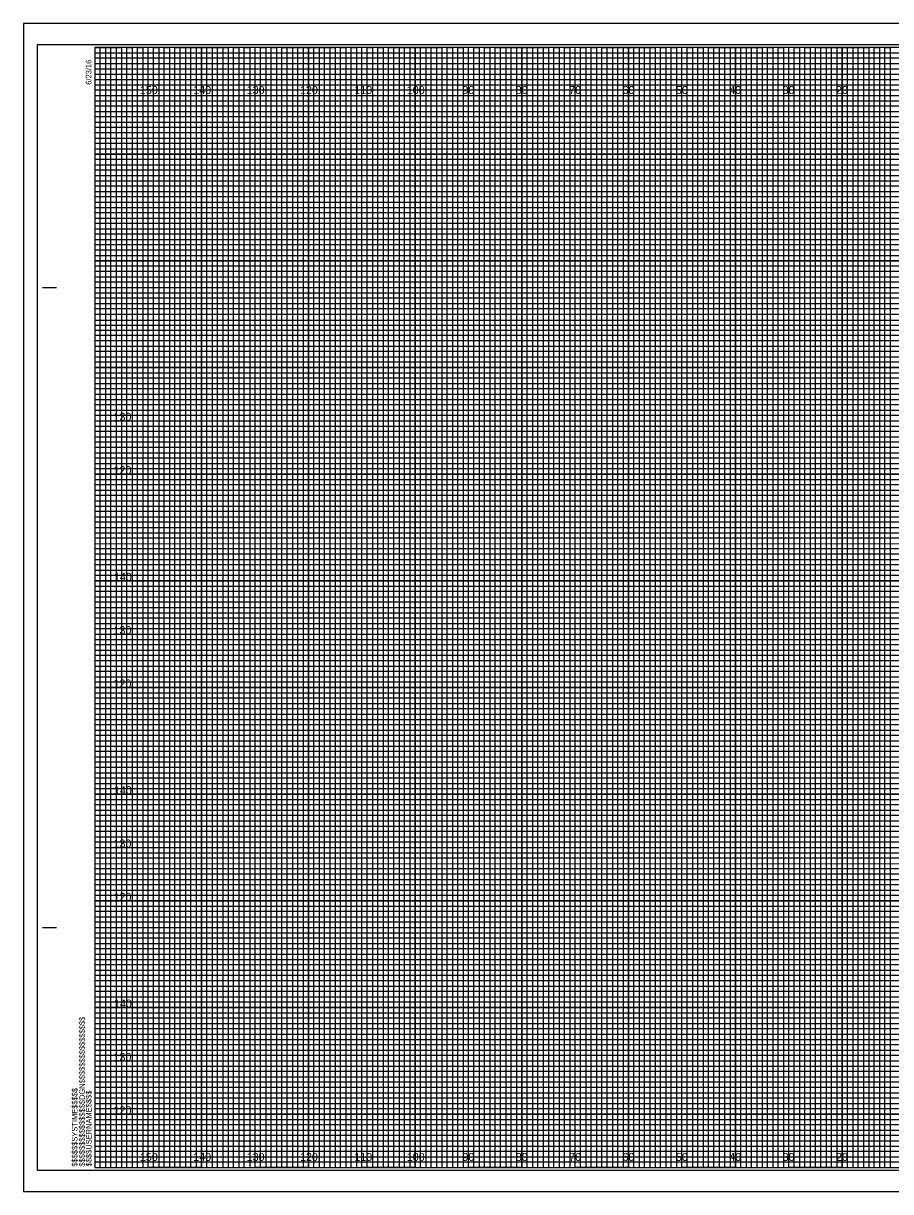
# Model space of a CAD drawing. Extents: x -13 to 323, y -5 to 215.
# Drawn here: x -13.4 to 149.1, y -4.5 to 214.5 of the extents above; entities that cross this region are included whole.
import ezdxf

# ---------------------------------------------------------------- set-up
doc = ezdxf.new("R2010")
doc.units = 0
for name, color, linetype in [('Exist CMT Pavement', 7, 'Continuous'), ('Exist Cross Section Cell', 7, 'Continuous'), ('Exist XS Center Line Elevation Label', 7, 'Continuous'), ('Exist XS Ground Line', 7, 'Continuous'), ('Prop CMT Concrete Structures', 7, 'Continuous'), ('Prop CMT Pvmt Course 1 Wedge', 7, 'Continuous'), ('Prop CMT Pvmt Course 2', 7, 'Continuous'), ('Prop CMT Pvmt Course 2 Wedge', 7, 'Continuous'), ('Prop CMT Pvmt Course 3', 7, 'Continuous'), ('Prop CMT Pvmt Course 3 Wedge', 7, 'Continuous'), ('Scratch_Level_0', 7, 'Continuous')]:
    doc.layers.add(name, color=color, linetype=linetype)

msp = doc.modelspace()

# ---------------------------------------------------------------- linework, layer by layer
at = {"layer": 'Exist XS Center Line Elevation Label'}
for points in [[(0, 210), (5, 210), (5, 0), (15, 0), (15, 210), (25, 210), (25, 0), (35, 0), (35, 210), (45, 210), (45, 0), (55, 0), (55, 210), (65, 210), (65, 0), (75, 0), (75, 210), (85, 210), (85, 0), (95, 0), (95, 210), (105, 210), (105, 0), (115, 0), (115, 210), (125, 210), (125, 0), (135, 0), (135, 210), (145, 210), (145, 0), (155, 0)], [(0, 205), (275, 205)], [(0, 185), (320, 185), (320, 195), (0, 195)], [(0, 165), (320, 165), (320, 175), (0, 175)], [(0, 145), (320, 145), (320, 155), (0, 155)], [(0, 125), (320, 125), (320, 135), (0, 135)], [(0, 105), (320, 105), (320, 115), (0, 115)], [(0, 85), (320, 85), (320, 95), (0, 95)], [(0, 65), (320, 65), (320, 75), (0, 75)], [(0, 45), (320, 45), (320, 55), (0, 55)], [(0, 25), (320, 25), (320, 35), (0, 35)], [(0, 5), (320, 5), (320, 15), (0, 15)]]:
    msp.add_lwpolyline(points, dxfattribs=at)
at = {"layer": 'Exist XS Ground Line'}
for p, q in [((10, 210), (0, 210)), ((10, 0), (10, 210)), ((30, 210), (20, 210)), ((20, 210), (20, 0)), ((30, 0), (30, 210)), ((50, 210), (40, 210)), ((40, 210), (40, 0)), ((50, 0), (50, 210)), ((70, 210), (60, 210)), ((60, 210), (60, 0)), ((70, 0), (70, 210)), ((90, 210), (80, 210)), ((80, 210), (80, 0)), ((90, 0), (90, 210)), ((110, 210), (100, 210)), ((100, 210), (100, 0)), ((110, 0), (110, 210)), ((130, 210), (120, 210)), ((120, 210), (120, 0)), ((130, 0), (130, 210)), ((150, 210), (140, 210)), ((140, 210), (140, 0)), ((20, 0), (10, 0)), ((40, 0), (30, 0)), ((60, 0), (50, 0)), ((80, 0), (70, 0)), ((100, 0), (90, 0)), ((120, 0), (110, 0)), ((140, 0), (130, 0))]:
    msp.add_line(p, q, dxfattribs=at)
for points in [[(0, 200), (320, 200), (320, 190), (0, 190)], [(0, 180), (320, 180), (320, 170), (0, 170)], [(0, 160), (320, 160), (320, 150), (0, 150)], [(0, 140), (320, 140), (320, 130), (0, 130)], [(0, 120), (320, 120), (320, 110), (0, 110)], [(0, 100), (320, 100), (320, 90), (0, 90)], [(0, 80), (320, 80), (320, 70), (0, 70)], [(0, 60), (320, 60), (320, 50), (0, 50)], [(0, 40), (320, 40), (320, 30), (0, 30)], [(0, 20), (320, 20), (320, 10), (0, 10)]]:
    msp.add_lwpolyline(points, dxfattribs=at)
at = {"layer": 'Prop CMT Concrete Structures'}
for p, q in [((323.3, 214.5), (-13.4, 214.5)), ((-13.4, 214.5), (-13.4, -4.5)), ((-13.4, -4.5), (323.3, -4.5))]:
    msp.add_line(p, q, dxfattribs=at)
at = {"layer": 'Prop CMT Pvmt Course 1 Wedge'}
msp.add_lwpolyline([(-13.4, -4.5), (323.3, -4.5), (323.3, 214.5), (-13.4, 214.5)], close=True, dxfattribs=at)
at = {"layer": 'Prop CMT Pvmt Course 2'}
for p, q in [((-9.8, 165), (-7.3, 165)), ((-9.7, 165), (-7.2, 165)), ((-9.8, 45), (-7.3, 45)), ((-9.7, 45), (-7.2, 45)), ((0, 0), (0, 0)), ((0, 0), (0, 0)), ((0, 0), (0, 0)), ((0, 0), (0, 0)), ((0, 0), (0, 0)), ((0, 0), (0, 0)), ((0, 0), (0, 0))]:
    msp.add_line(p, q, dxfattribs=at)
msp.add_lwpolyline([(320, 210), (0, 210), (0, 0), (320, 0)], close=True, dxfattribs=at)
at = {"layer": 'Prop CMT Pvmt Course 2 Wedge'}
msp.add_lwpolyline([(-10.8, -0.5), (322.4, -0.5), (322.4, 210.5), (-10.8, 210.5)], close=True, dxfattribs=at)
at = {"layer": 'Prop CMT Pvmt Course 3'}
for points in [[(0, 0), (1, 0), (1, 210), (2, 210), (2, 0)], [(2, 0), (3, 0), (3, 210), (4, 210), (4, 0)], [(5, 0), (6, 0), (6, 210), (7, 210), (7, 0)], [(7, 0), (8, 0), (8, 210), (9, 210), (9, 0)], [(10, 0), (11, 0), (11, 210), (12, 210), (12, 0)], [(12, 0), (13, 0), (13, 210), (14, 210), (14, 0)], [(15, 0), (16, 0), (16, 210), (17, 210), (17, 0)], [(17, 0), (18, 0), (18, 210), (19, 210), (19, 0)], [(20, 0), (21, 0), (21, 210), (22, 210), (22, 0)], [(22, 0), (23, 0), (23, 210), (24, 210), (24, 0)], [(25, 0), (26, 0), (26, 210), (27, 210), (27, 0)], [(27, 0), (28, 0), (28, 210), (29, 210), (29, 0)], [(30, 0), (31, 0), (31, 210), (32, 210), (32, 0)], [(32, 0), (33, 0), (33, 210), (34, 210), (34, 0)], [(35, 0), (36, 0), (36, 210), (37, 210), (37, 0)], [(37, 0), (38, 0), (38, 210), (39, 210), (39, 0)], [(40, 0), (41, 0), (41, 210), (42, 210), (42, 0)], [(42, 0), (43, 0), (43, 210), (44, 210), (44, 0)], [(45, 0), (46, 0), (46, 210), (47, 210), (47, 0)], [(47, 0), (48, 0), (48, 210), (49, 210), (49, 0)], [(50, 0), (51, 0), (51, 210), (52, 210), (52, 0)], [(52, 0), (53, 0), (53, 210), (54, 210), (54, 0)], [(55, 0), (56, 0), (56, 210), (57, 210), (57, 0)], [(57, 0), (58, 0), (58, 210), (59, 210), (59, 0)], [(60, 0), (61, 0), (61, 210), (62, 210), (62, 0)], [(62, 0), (63, 0), (63, 210), (64, 210), (64, 0)], [(65, 0), (66, 0), (66, 210), (67, 210), (67, 0)], [(67, 0), (68, 0), (68, 210), (69, 210), (69, 0)], [(70, 0), (71, 0), (71, 210), (72, 210), (72, 0)], [(72, 0), (73, 0), (73, 210), (74, 210), (74, 0)], [(75, 0), (76, 0), (76, 210), (77, 210), (77, 0)], [(77, 0), (78, 0), (78, 210), (79, 210), (79, 0)], [(80, 0), (81, 0), (81, 210), (82, 210), (82, 0)], [(82, 0), (83, 0), (83, 210), (84, 210), (84, 0)], [(85, 0), (86, 0), (86, 210), (87, 210), (87, 0)], [(87, 0), (88, 0), (88, 210), (89, 210), (89, 0)], [(90, 0), (91, 0), (91, 210), (92, 210), (92, 0)], [(92, 0), (93, 0), (93, 210), (94, 210), (94, 0)], [(95, 0), (96, 0), (96, 210), (97, 210), (97, 0)], [(97, 0), (98, 0), (98, 210), (99, 210), (99, 0)], [(100, 0), (101, 0), (101, 210), (102, 210), (102, 0)], [(102, 0), (103, 0), (103, 210), (104, 210), (104, 0)], [(105, 0), (106, 0), (106, 210), (107, 210), (107, 0)], [(107, 0), (108, 0), (108, 210), (109, 210), (109, 0)], [(110, 0), (111, 0), (111, 210), (112, 210), (112, 0)], [(112, 0), (113, 0), (113, 210), (114, 210), (114, 0)], [(115, 0), (116, 0), (116, 210), (117, 210), (117, 0)], [(117, 0), (118, 0), (118, 210), (119, 210), (119, 0)], [(120, 0), (121, 0), (121, 210), (122, 210), (122, 0)], [(122, 0), (123, 0), (123, 210), (124, 210), (124, 0)], [(125, 0), (126, 0), (126, 210), (127, 210), (127, 0)], [(127, 0), (128, 0), (128, 210), (129, 210), (129, 0)], [(130, 0), (131, 0), (131, 210), (132, 210), (132, 0)], [(132, 0), (133, 0), (133, 210), (134, 210), (134, 0)], [(135, 0), (136, 0), (136, 210), (137, 210), (137, 0)], [(137, 0), (138, 0), (138, 210), (139, 210), (139, 0)], [(140, 0), (141, 0), (141, 210), (142, 210), (142, 0)], [(142, 0), (143, 0), (143, 210), (144, 210), (144, 0)], [(145, 0), (146, 0), (146, 210), (147, 210), (147, 0)], [(147, 0), (148, 0), (148, 210), (149, 210), (149, 0)]]:
    msp.add_lwpolyline(points, dxfattribs=at)
at = {"layer": 'Prop CMT Pvmt Course 3 Wedge'}
for p, q in [((10, 0), (10, 210)), ((20, 0), (20, 210)), ((30, 0), (30, 210)), ((40, 0), (40, 210)), ((50, 0), (50, 210)), ((60, 0), (60, 210)), ((70, 0), (70, 210)), ((80, 0), (80, 210)), ((90, 0), (90, 210)), ((100, 0), (100, 210)), ((110, 0), (110, 210)), ((120, 0), (120, 210)), ((130, 0), (130, 210)), ((140, 0), (140, 210)), ((0, 200), (320, 200)), ((0, 190), (320, 190)), ((0, 180), (320, 180)), ((0, 170), (320, 170)), ((0, 160), (320, 160)), ((0, 150), (320, 150)), ((0, 140), (320, 140)), ((0, 130), (320, 130)), ((0, 120), (320, 120)), ((0, 110), (320, 110)), ((0, 100), (320, 100)), ((0, 90), (320, 90)), ((0, 80), (320, 80)), ((0, 70), (320, 70)), ((0, 60), (320, 60)), ((0, 50), (320, 50)), ((0, 40), (320, 40)), ((0, 30), (320, 30)), ((0, 20), (320, 20)), ((0, 10), (320, 10))]:
    msp.add_line(p, q, dxfattribs=at)
at = {"layer": 'Scratch_Level_0'}
for p, q in [((0, 209), (260, 209)), ((260, 207.98), (0, 207.98)), ((0, 207.98), (0, 207)), ((0, 207), (260, 207)), ((260, 205.89), (0, 205.89)), ((0, 205.89), (0, 204)), ((0, 204), (320, 204))]:
    msp.add_line(p, q, dxfattribs=at)
for points in [[(0, 203), (270, 203), (320, 203), (320, 202), (0, 202)], [(0, 201), (320, 201), (320, 199), (0, 199)], [(0, 198), (320, 198), (320, 197), (0, 196.98)], [(0, 196), (320, 196), (320, 194), (0, 194)], [(0, 193), (320, 193), (320, 192), (0, 192)], [(0, 191), (320, 191), (320, 189), (0, 189)], [(0, 188), (320, 188), (320, 187), (0, 187)], [(0, 186), (320, 186), (320, 184), (0, 184)], [(0, 183), (320, 183), (320, 182), (0, 182)], [(0, 181), (320, 181), (320, 179), (0, 179)], [(0, 178), (320, 178), (320, 177), (0, 177)], [(0, 176), (320, 176), (320, 173.95), (320, 173), (320, 172), (0, 172)], [(0, 174), (320, 174), (320, 173), (0, 173)], [(0, 171), (320, 171), (320, 169), (0, 169.03)], [(0, 169.03), (320, 169), (320, 168), (0, 168)], [(0, 167), (320, 167), (320, 166), (0, 166)], [(0, 164), (320, 164), (320, 163), (0, 163)], [(0, 162), (320, 162), (320, 161), (0, 161)], [(-0.07, 158.89), (320, 158.89), (320, 157.88), (-0.07, 157.88)], [(0, 157), (320, 157), (320, 156), (0, 156)], [(0, 154), (320, 154), (320, 153), (0, 153)], [(0, 152), (320, 152), (320, 151), (0, 151)], [(0, 149), (320, 149), (320, 148), (0, 148)], [(0, 147), (320, 147), (320, 146), (0, 146)], [(0, 144), (320, 144), (320, 143), (0, 143)], [(0, 142), (320, 142), (320, 141), (0, 141)], [(0, 139), (320, 139), (319.99, 137.98), (0, 138)], [(0, 137), (320, 137), (320, 136), (0, 136)], [(0, 134), (320, 134), (320, 133), (0, 133)], [(0, 132), (320, 132), (320, 131), (0, 131)], [(0, 129), (320, 129), (320, 128), (0, 128)], [(0, 127), (320, 127), (320, 126), (0, 126)], [(0, 124), (320, 124), (320, 123), (0, 123)], [(0, 122), (320, 122), (320, 121), (0, 121)], [(0, 119), (320, 119), (320, 118), (0, 118)], [(0, 116.99), (320.07, 116.91), (320, 116), (0, 116)], [(0, 114), (320, 114), (320, 113), (0, 113)], [(0, 112), (320, 112), (320, 111), (0, 111)], [(0, 109), (320, 109), (320, 108), (0, 108)], [(0, 107), (320, 107), (320, 106), (0, 106)], [(0, 104), (320, 104), (320, 103), (0, 103)], [(0, 102), (320, 102), (320, 101), (0, 101)], [(0, 99), (320, 99), (320, 98), (0, 98)], [(0, 97), (320, 97), (320, 96), (0, 96)], [(0, 94), (320, 94), (320, 93), (0, 93)], [(0, 92), (320, 92), (320, 91), (0, 91)], [(0, 89), (320, 89), (320, 88), (0, 88)], [(0, 87), (320, 87), (320, 86), (0, 86)], [(0, 84), (320, 84), (320, 83), (0, 83)], [(0, 82), (320, 82), (320, 81), (0, 81)], [(0, 79), (320, 79), (319.99, 77.98), (0, 78)], [(0, 77), (320, 77), (320, 76), (0, 76)], [(0, 74), (320, 74), (320, 73), (0, 73)], [(0, 72), (320, 72), (320, 71), (0, 71)], [(0, 69), (320, 69), (320, 68), (0, 68)], [(0, 67), (320, 67), (320, 66), (0, 66)], [(0, 64), (320, 64), (320, 63), (0, 63)], [(0, 62), (320, 62), (320, 61), (0, 61)], [(0, 59), (320, 59), (320, 58), (0, 58)], [(0, 56.99), (320.07, 56.91), (320, 56), (0, 56)], [(0, 54), (320, 54), (320, 53), (0, 53)], [(0, 52), (320, 52), (320, 51), (0, 51)], [(0, 49), (320, 49), (320, 48), (0, 48)], [(0, 47), (320, 47), (320, 46), (0, 46)], [(0, 44), (320, 44), (320, 43), (0, 43)], [(0, 42), (320, 42), (320, 41), (0, 41)], [(0, 39), (320, 39), (320, 38), (0, 38)], [(0, 37), (320, 37), (320, 36), (0, 36)], [(0, 34), (320, 34), (320, 33), (0, 33)], [(0, 32), (320, 32), (320, 31), (0, 31)], [(0, 29), (320, 29), (320, 28), (0, 28)], [(0, 27), (320, 27), (320, 26), (0, 26)], [(0, 24), (320, 24), (320, 23), (0, 23)], [(0, 22), (320, 22), (320, 21), (0, 21)], [(0, 19), (320, 19), (320, 18), (0, 18)], [(0, 17), (320, 17), (320, 16), (0, 16)], [(0, 14), (320, 14), (320, 13), (0, 13)], [(0, 12), (320, 12), (320, 11), (0, 11)], [(0, 9), (320, 9), (320, 8), (0, 8)], [(0, 7), (320, 7), (320, 6), (0, 6)], [(0, 4), (320, 4), (320, 3), (0, 3)], [(0, 2), (320, 2), (320, 1), (0, 1)]]:
    msp.add_lwpolyline(points, dxfattribs=at)

# ---------------------------------------------------------------- texts
at = {"layer": 'Exist CMT Pavement'}
for s, p in [('130', (3.49, 140)), ('120', (3.5, 130)), ('140', (3.57, 110)), ('130', (3.49, 100)), ('120', (3.5, 90)), ('140', (3.57, 70)), ('130', (3.49, 60)), ('120', (3.5, 50)), ('140', (3.57, 30)), ('130', (3.49, 20)), ('120', (3.5, 10))]:
    msp.add_text(s, height=1.5, dxfattribs=at).set_placement(p)
at = {"layer": 'Exist Cross Section Cell'}
for s, p in [('150', (8.44, 201.25)), ('140', (18.44, 201.25)), ('130', (28.44, 201.25)), ('120', (38.44, 201.25)), ('110', (48.62, 201.25)), ('100', (58.44, 201.25)), ('90', (68.86, 201.25)), ('80', (78.86, 201.25)), ('70', (88.86, 201.25)), ('60', (98.86, 201.25)), ('50', (108.86, 201.25)), ('40', (118.86, 201.25)), ('30', (128.86, 201.25)), ('20', (138.86, 201.25)), ('150', (8.44, 1.25)), ('140', (18.44, 1.25)), ('130', (28.44, 1.25)), ('120', (38.44, 1.25)), ('110', (48.62, 1.25)), ('100', (58.44, 1.25)), ('90', (68.86, 1.25)), ('80', (78.86, 1.25)), ('70', (88.86, 1.25)), ('60', (98.86, 1.25)), ('50', (108.86, 1.25)), ('40', (118.86, 1.25)), ('30', (128.86, 1.25)), ('20', (138.86, 1.25))]:
    msp.add_text(s, height=1.5, dxfattribs=at).set_placement(p)
at = {"layer": 'Prop CMT Pvmt Course 2'}
for s, p in [('6/23/16', (-0.65, 203)), ('$$$$$$$$$$$$$$$$DGN$$$$$$$$$$$$$$$$', (-1.88, 0.18)), ('$$$$$$SYSTIME$$$$$', (-3.26, 0.18)), ('$$$$USERNAME$$$$', (-0.62, 0.23))]:
    msp.add_text(s, height=1.05, rotation=90, dxfattribs=at).set_placement(p)

doc.saveas('drawing.dxf')
